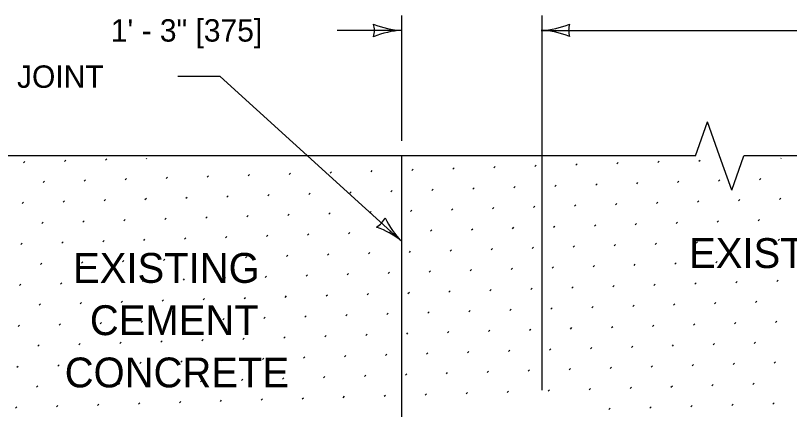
# Model space of a CAD drawing. Extents: x 49991.4 to 50021, y 49987.6 to 50011.4.
# Drawn here: x 50001.323 to 50003.394, y 49992.125 to 49993.18 of the extents above; entities that cross this region are included whole.
import ezdxf

# ---------------------------------------------------------------- set-up
doc = ezdxf.new("R2010")
doc.units = 0
for name, color, linetype in [('Level 1', 7, 'Continuous'), ('Level 10', 7, 'Continuous'), ('Level 2', 7, 'Continuous'), ('Level 3', 7, 'Continuous'), ('Level 6', 7, 'Continuous')]:
    doc.layers.add(name, color=color, linetype=linetype)

msp = doc.modelspace()

# ---------------------------------------------------------------- linework, layer by layer
at = {"layer": 'Level 1'}
msp.add_line((50002.3571, 49991.8039), (50002.3571, 49992.8039), dxfattribs=at)
at = {"layer": 'Level 10'}
for p, q in [((50001.8712, 49993.0162), (50001.7573, 49993.0162)), ((50002.3571, 49992.5747), (50001.8712, 49993.0162)), ((50001.3446, 49992.7857), (50001.3481, 49992.7893)), ((50001.4542, 49992.7893), (50001.4577, 49992.7928)), ((50001.5638, 49992.7928), (50001.5673, 49992.7964)), ((50001.6734, 49992.7964), (50001.6745, 49992.7974)), ((50002.8225, 49992.7788), (50002.826, 49992.7823)), ((50002.9321, 49992.7823), (50002.9357, 49992.7858)), ((50003.0417, 49992.7858), (50003.0453, 49992.7894)), ((50003.1513, 49992.7894), (50003.1549, 49992.7929)), ((50003.3706, 49992.7965), (50003.3715, 49992.7974)), ((50002.1649, 49992.7575), (50002.1684, 49992.761)), ((50002.2745, 49992.761), (50002.278, 49992.7646)), ((50002.3841, 49992.7646), (50002.3876, 49992.7681)), ((50002.4937, 49992.7681), (50002.4972, 49992.7717)), ((50002.6033, 49992.7717), (50002.6068, 49992.7752)), ((50002.7129, 49992.7752), (50002.7164, 49992.7787)), ((50001.5072, 49992.7362), (50001.5107, 49992.7398)), ((50001.6168, 49992.7398), (50001.6204, 49992.7433)), ((50001.7264, 49992.7433), (50001.73, 49992.7469)), ((50001.836, 49992.7469), (50001.8396, 49992.7504)), ((50001.9456, 49992.7504), (50001.9492, 49992.7539)), ((50002.0553, 49992.754), (50002.0588, 49992.7575)), ((50003.2044, 49992.7363), (50003.2079, 49992.7399)), ((50003.314, 49992.7399), (50003.3175, 49992.7434)), ((50001.3976, 49992.7327), (50001.4011, 49992.7362)), ((50002.5467, 49992.7151), (50002.5503, 49992.7186)), ((50002.6563, 49992.7186), (50002.6599, 49992.7222)), ((50002.7659, 49992.7222), (50002.7695, 49992.7257)), ((50002.8755, 49992.7257), (50002.8791, 49992.7293)), ((50002.9852, 49992.7293), (50002.9887, 49992.7328)), ((50003.0948, 49992.7328), (50003.0983, 49992.7363)), ((50001.8891, 49992.6938), (50001.8926, 49992.6974)), ((50001.9987, 49992.6974), (50002.0022, 49992.7009)), ((50002.1083, 49992.7009), (50002.1118, 49992.7045)), ((50002.2179, 49992.7045), (50002.2214, 49992.708)), ((50002.3275, 49992.708), (50002.331, 49992.7115)), ((50002.4371, 49992.7115), (50002.4406, 49992.7151)), ((50001.341, 49992.6761), (50001.3446, 49992.6797)), ((50001.4506, 49992.6797), (50001.4542, 49992.6832)), ((50001.5602, 49992.6832), (50001.5638, 49992.6867)), ((50001.6698, 49992.6867), (50001.6734, 49992.6903)), ((50001.7795, 49992.6903), (50001.783, 49992.6938)), ((50003.0382, 49992.6762), (50003.0417, 49992.6798)), ((50003.1478, 49992.6798), (50003.1513, 49992.6833)), ((50003.2574, 49992.6833), (50003.2609, 49992.6868)), ((50003.367, 49992.6869), (50003.3705, 49992.6904)), ((50002.3805, 49992.655), (50002.3841, 49992.6585)), ((50002.4901, 49992.6585), (50002.4937, 49992.662)), ((50002.5998, 49992.6621), (50002.6033, 49992.6656)), ((50002.7094, 49992.6656), (50002.7129, 49992.6691)), ((50002.819, 49992.6691), (50002.8225, 49992.6727)), ((50002.9286, 49992.6727), (50002.9321, 49992.6762)), ((50001.7229, 49992.6337), (50001.7264, 49992.6373)), ((50001.8325, 49992.6373), (50001.836, 49992.6408)), ((50001.9421, 49992.6408), (50001.9456, 49992.6443)), ((50002.0517, 49992.6443), (50002.0552, 49992.6479)), ((50002.1613, 49992.6479), (50002.1649, 49992.6514)), ((50002.2709, 49992.6514), (50002.2745, 49992.655)), ((50001.3941, 49992.6231), (50001.3976, 49992.6266)), ((50001.5037, 49992.6266), (50001.5072, 49992.6302)), ((50001.6133, 49992.6302), (50001.6168, 49992.6337)), ((50002.7624, 49992.6126), (50002.7659, 49992.6161)), ((50002.872, 49992.6161), (50002.8755, 49992.6196)), ((50002.9816, 49992.6197), (50002.9851, 49992.6232)), ((50003.0912, 49992.6232), (50003.0948, 49992.6267)), ((50003.2008, 49992.6267), (50003.2044, 49992.6303)), ((50003.3104, 49992.6303), (50003.314, 49992.6338)), ((50002.1047, 49992.5913), (50002.1083, 49992.5948)), ((50002.2143, 49992.5949), (50002.2179, 49992.5984)), ((50002.324, 49992.5984), (50002.3275, 49992.6019)), ((50002.4336, 49992.6019), (50002.4371, 49992.6055)), ((50002.5432, 49992.6055), (50002.5467, 49992.609)), ((50002.6528, 49992.609), (50002.6563, 49992.6126)), ((50001.4471, 49992.5701), (50001.4506, 49992.5736)), ((50001.5567, 49992.5736), (50001.5602, 49992.5771)), ((50001.6663, 49992.5771), (50001.6698, 49992.5807)), ((50001.7759, 49992.5807), (50001.7795, 49992.5842)), ((50001.8855, 49992.5842), (50001.8891, 49992.5878)), ((50001.9951, 49992.5878), (50001.9987, 49992.5913)), ((50003.1443, 49992.5702), (50003.1478, 49992.5737)), ((50003.2539, 49992.5737), (50003.2574, 49992.5772)), ((50003.3635, 49992.5772), (50003.367, 49992.5808)), ((50001.3375, 49992.5665), (50001.341, 49992.57)), ((50002.4866, 49992.5489), (50002.4901, 49992.5524)), ((50002.5962, 49992.5524), (50002.5997, 49992.556)), ((50002.7058, 49992.556), (50002.7094, 49992.5595)), ((50002.8154, 49992.5595), (50002.819, 49992.5631)), ((50002.925, 49992.5631), (50002.9286, 49992.5666)), ((50003.0346, 49992.5666), (50003.0382, 49992.5702)), ((50001.9386, 49992.5312), (50001.9421, 49992.5347)), ((50002.0482, 49992.5347), (50002.0517, 49992.5383)), ((50002.1578, 49992.5383), (50002.1613, 49992.5418)), ((50002.2674, 49992.5418), (50002.2709, 49992.5454)), ((50002.377, 49992.5454), (50002.3805, 49992.5489)), ((50001.3905, 49992.5135), (50001.394, 49992.517)), ((50001.5001, 49992.517), (50001.5037, 49992.5206)), ((50001.6097, 49992.5206), (50001.6133, 49992.5241)), ((50001.7193, 49992.5241), (50001.7229, 49992.5276)), ((50001.8289, 49992.5276), (50001.8325, 49992.5312)), ((50002.9781, 49992.51), (50002.9816, 49992.5136)), ((50003.0877, 49992.5136), (50003.0912, 49992.5171)), ((50003.1973, 49992.5171), (50003.2008, 49992.5207)), ((50003.3069, 49992.5207), (50003.3104, 49992.5242)), ((50002.3204, 49992.4888), (50002.324, 49992.4923)), ((50002.43, 49992.4923), (50002.4336, 49992.4959)), ((50002.5396, 49992.4959), (50002.5432, 49992.4994)), ((50002.6492, 49992.4994), (50002.6528, 49992.503)), ((50002.7588, 49992.503), (50002.7624, 49992.5065)), ((50002.8685, 49992.5065), (50002.872, 49992.51)), ((50001.6628, 49992.4675), (50001.6663, 49992.4711)), ((50001.7724, 49992.4711), (50001.7759, 49992.4746)), ((50001.882, 49992.4746), (50001.8855, 49992.4782)), ((50001.9916, 49992.4782), (50001.9951, 49992.4817)), ((50002.1012, 49992.4817), (50002.1047, 49992.4852)), ((50002.2108, 49992.4852), (50002.2143, 49992.4888)), ((50003.3599, 49992.4676), (50003.3635, 49992.4712)), ((50001.3339, 49992.4569), (50001.3375, 49992.4604)), ((50001.4435, 49992.4604), (50001.4471, 49992.464)), ((50001.5532, 49992.464), (50001.5567, 49992.4675)), ((50002.7023, 49992.4464), (50002.7058, 49992.4499)), ((50002.8119, 49992.4499), (50002.8154, 49992.4535)), ((50002.9215, 49992.4535), (50002.925, 49992.457)), ((50003.0311, 49992.457), (50003.0346, 49992.4605)), ((50003.1407, 49992.4606), (50003.1442, 49992.4641)), ((50003.2503, 49992.4641), (50003.2539, 49992.4676)), ((50002.0446, 49992.4251), (50002.0482, 49992.4287)), ((50002.1542, 49992.4287), (50002.1578, 49992.4322)), ((50002.2638, 49992.4322), (50002.2674, 49992.4357)), ((50002.3734, 49992.4358), (50002.377, 49992.4393)), ((50002.4831, 49992.4393), (50002.4866, 49992.4428)), ((50002.5927, 49992.4428), (50002.5962, 49992.4464)), ((50001.387, 49992.4039), (50001.3905, 49992.4074)), ((50001.4966, 49992.4074), (50001.5001, 49992.4109)), ((50001.6062, 49992.411), (50001.6097, 49992.4145)), ((50001.7158, 49992.4145), (50001.7193, 49992.418)), ((50001.8254, 49992.418), (50001.8289, 49992.4216)), ((50001.935, 49992.4216), (50001.9385, 49992.4251)), ((50003.0841, 49992.404), (50003.0877, 49992.4075)), ((50003.1937, 49992.4075), (50003.1973, 49992.4111)), ((50003.3034, 49992.4111), (50003.3069, 49992.4146)), ((50002.5361, 49992.3863), (50002.5396, 49992.3898)), ((50002.6457, 49992.3898), (50002.6492, 49992.3933)), ((50002.7553, 49992.3933), (50002.7588, 49992.3969)), ((50002.8649, 49992.3969), (50002.8685, 49992.4004)), ((50002.9745, 49992.4004), (50002.9781, 49992.404)), ((50001.8784, 49992.365), (50001.882, 49992.3685)), ((50001.988, 49992.3686), (50001.9916, 49992.3721)), ((50002.0977, 49992.3721), (50002.1012, 49992.3756)), ((50002.2073, 49992.3756), (50002.2108, 49992.3792)), ((50002.3169, 49992.3792), (50002.3204, 49992.3827)), ((50002.4265, 49992.3827), (50002.43, 49992.3863)), ((50001.3304, 49992.3473), (50001.3339, 49992.3508)), ((50001.44, 49992.3508), (50001.4435, 49992.3544)), ((50001.5496, 49992.3544), (50001.5531, 49992.3579)), ((50001.6592, 49992.3579), (50001.6628, 49992.3615)), ((50001.7688, 49992.3615), (50001.7724, 49992.365)), ((50002.9179, 49992.3439), (50002.9215, 49992.3474)), ((50003.0276, 49992.3474), (50003.0311, 49992.3509)), ((50003.1372, 49992.3509), (50003.1407, 49992.3545)), ((50003.2468, 49992.3545), (50003.2503, 49992.358)), ((50003.3564, 49992.358), (50003.3599, 49992.3616)), ((50002.2603, 49992.3226), (50002.2638, 49992.3261)), ((50002.3699, 49992.3261), (50002.3734, 49992.3297)), ((50002.4795, 49992.3297), (50002.483, 49992.3332)), ((50002.5891, 49992.3332), (50002.5927, 49992.3368)), ((50002.6987, 49992.3368), (50002.7023, 49992.3403)), ((50002.8083, 49992.3403), (50002.8119, 49992.3439)), ((50001.6026, 49992.3013), (50001.6062, 49992.3049)), ((50001.7123, 49992.3049), (50001.7158, 49992.3084)), ((50001.8219, 49992.3084), (50001.8254, 49992.312)), ((50001.9315, 49992.312), (50001.935, 49992.3155)), ((50002.0411, 49992.3155), (50002.0446, 49992.3191)), ((50002.1507, 49992.3191), (50002.1542, 49992.3226)), ((50003.2998, 49992.3015), (50003.3033, 49992.305)), ((50001.3834, 49992.2943), (50001.387, 49992.2978)), ((50001.493, 49992.2978), (50001.4966, 49992.3013)), ((50002.6422, 49992.2802), (50002.6457, 49992.2837)), ((50002.7518, 49992.2837), (50002.7553, 49992.2873)), ((50002.8614, 49992.2873), (50002.8649, 49992.2908)), ((50002.971, 49992.2908), (50002.9745, 49992.2944)), ((50003.0806, 49992.2944), (50003.0841, 49992.2979)), ((50003.1902, 49992.2979), (50003.1937, 49992.3014)), ((50001.9845, 49992.2589), (50001.988, 49992.2625)), ((50002.0941, 49992.2625), (50002.0976, 49992.266)), ((50002.2037, 49992.266), (50002.2073, 49992.2696)), ((50002.3133, 49992.2696), (50002.3169, 49992.2731)), ((50002.4229, 49992.2731), (50002.4265, 49992.2766)), ((50002.5325, 49992.2767), (50002.5361, 49992.2802)), ((50001.4365, 49992.2412), (50001.44, 49992.2448)), ((50001.5461, 49992.2448), (50001.5496, 49992.2483)), ((50001.6557, 49992.2483), (50001.6592, 49992.2518)), ((50001.7653, 49992.2519), (50001.7688, 49992.2554)), ((50001.8749, 49992.2554), (50001.8784, 49992.2589)), ((50003.1336, 49992.2413), (50003.1372, 49992.2449)), ((50003.2432, 49992.2449), (50003.2468, 49992.2484)), ((50003.3528, 49992.2484), (50003.3564, 49992.252)), ((50001.3269, 49992.2377), (50001.3304, 49992.2412)), ((50002.476, 49992.2201), (50002.4795, 49992.2236)), ((50002.5856, 49992.2236), (50002.5891, 49992.2272)), ((50002.6952, 49992.2272), (50002.6987, 49992.2307)), ((50002.8048, 49992.2307), (50002.8083, 49992.2342)), ((50002.9144, 49992.2342), (50002.9179, 49992.2378)), ((50003.024, 49992.2378), (50003.0276, 49992.2413)), ((50001.8183, 49992.1988), (50001.8219, 49992.2024)), ((50001.9279, 49992.2024), (50001.9315, 49992.2059)), ((50002.0375, 49992.2059), (50002.0411, 49992.2094)), ((50002.1471, 49992.2095), (50002.1507, 49992.213)), ((50002.2568, 49992.213), (50002.2603, 49992.2165)), ((50002.3664, 49992.2165), (50002.3699, 49992.2201)), ((50001.3799, 49992.1847), (50001.3834, 49992.1882)), ((50001.4895, 49992.1882), (50001.493, 49992.1917)), ((50001.5991, 49992.1917), (50001.6026, 49992.1953)), ((50001.7087, 49992.1953), (50001.7122, 49992.1988)), ((50002.8578, 49992.1777), (50002.8614, 49992.1812)), ((50002.9674, 49992.1812), (50002.971, 49992.1848)), ((50003.077, 49992.1848), (50003.0806, 49992.1883)), ((50003.1867, 49992.1883), (50003.1902, 49992.1918)), ((50003.2963, 49992.1918), (50003.2998, 49992.1954)), ((50002.2002, 49992.1564), (50002.2037, 49992.16)), ((50002.3098, 49992.16), (50002.3133, 49992.1635)), ((50002.4194, 49992.1635), (50002.4229, 49992.167)), ((50002.529, 49992.167), (50002.5325, 49992.1706)), ((50002.6386, 49992.1706), (50002.6421, 49992.1741)), ((50002.7482, 49992.1741), (50002.7518, 49992.1777)), ((50001.5425, 49992.1352), (50001.5461, 49992.1387)), ((50001.6521, 49992.1387), (50001.6557, 49992.1422)), ((50001.7617, 49992.1422), (50001.7653, 49992.1458)), ((50001.8714, 49992.1458), (50001.8749, 49992.1493)), ((50001.981, 49992.1493), (50001.9845, 49992.1529)), ((50002.0906, 49992.1529), (50002.0941, 49992.1564)), ((50003.2397, 49992.1353), (50003.2432, 49992.1388)), ((50003.3493, 49992.1388), (50003.3528, 49992.1423)), ((50001.3233, 49992.1281), (50001.3268, 49992.1316)), ((50001.4329, 49992.1316), (50001.4365, 49992.1352)), ((50002.9109, 49992.1246), (50002.9144, 49992.1282)), ((50003.0205, 49992.1282), (50003.024, 49992.1317)), ((50003.1301, 49992.1317), (50003.1336, 49992.1353))]:
    msp.add_line(p, q, dxfattribs=at)
at = {"layer": 'Level 3'}
for p, q in [((50002.3571, 49992.8439), (50002.3571, 49993.18)), ((50002.7321, 49992.1764), (50002.7321, 49993.18)), ((50002.3571, 49993.14), (50002.1836, 49993.14)), ((50002.7321, 49993.14), (50005.7321, 49993.14))]:
    msp.add_line(p, q, dxfattribs=at)
for centre, radius, start, end in [((50002.3662, 49993.3621), 0.2223, 247.4572, 267.6407), ((50002.2288, 49993.14), 0.0548, 342.14, 17.8624), ((50002.7183, 49993.3728), 0.233, 272.8285, 292.0784), ((50002.858, 49993.1401), 0.0548, 162.14, 197.8624), ((50002.3686, 49992.9073), 0.233, 92.8285, 112.0784), ((50002.7206, 49992.918), 0.2223, 67.4572, 87.6407), ((50002.2622, 49992.6609), 0.0548, 299.8801, 335.6024), ((50002.5132, 49992.7329), 0.2223, 205.1973, 225.3808), ((50002.2091, 49992.3947), 0.233, 50.5686, 69.8184)]:
    msp.add_arc(centre, radius, start, end, dxfattribs=at)
at = {"layer": 'Level 6'}
for p, q in [((50003.1423, 49992.8039), (50003.1747, 49992.8953)), ((50003.2071, 49992.8039), (50003.1747, 49992.8953)), ((50003.1423, 49992.8039), (50001.0571, 49992.8039)), ((50003.2395, 49992.7125), (50003.2071, 49992.8039)), ((50003.2395, 49992.7125), (50003.2719, 49992.8039)), ((50005.1923, 49992.8039), (50003.2719, 49992.8039))]:
    msp.add_line(p, q, dxfattribs=at)

# ---------------------------------------------------------------- texts
at = {"layer": 'Level 2'}
for s, height, p in [('1\' - 3" [375]', 0.06, (50001.5783, 49993.11)), ('EXISTING CEMENT CONCRETE PAVEMENT', 0.08, (50003.1255, 49992.5036)), ('EXISTING', 0.08, (50001.4774, 49992.4639)), ('CEMENT', 0.08, (50001.5223, 49992.3239)), ('CONCRETE', 0.08, (50001.455, 49992.1839))]:
    msp.add_text(s, height=height, dxfattribs=at).set_placement(p)
msp.add_text('EXISTING TRANSVERSE JOINT', height=0.06, rotation=360, dxfattribs=at).set_placement((50000.3644, 49992.9862))

doc.saveas('drawing.dxf')
